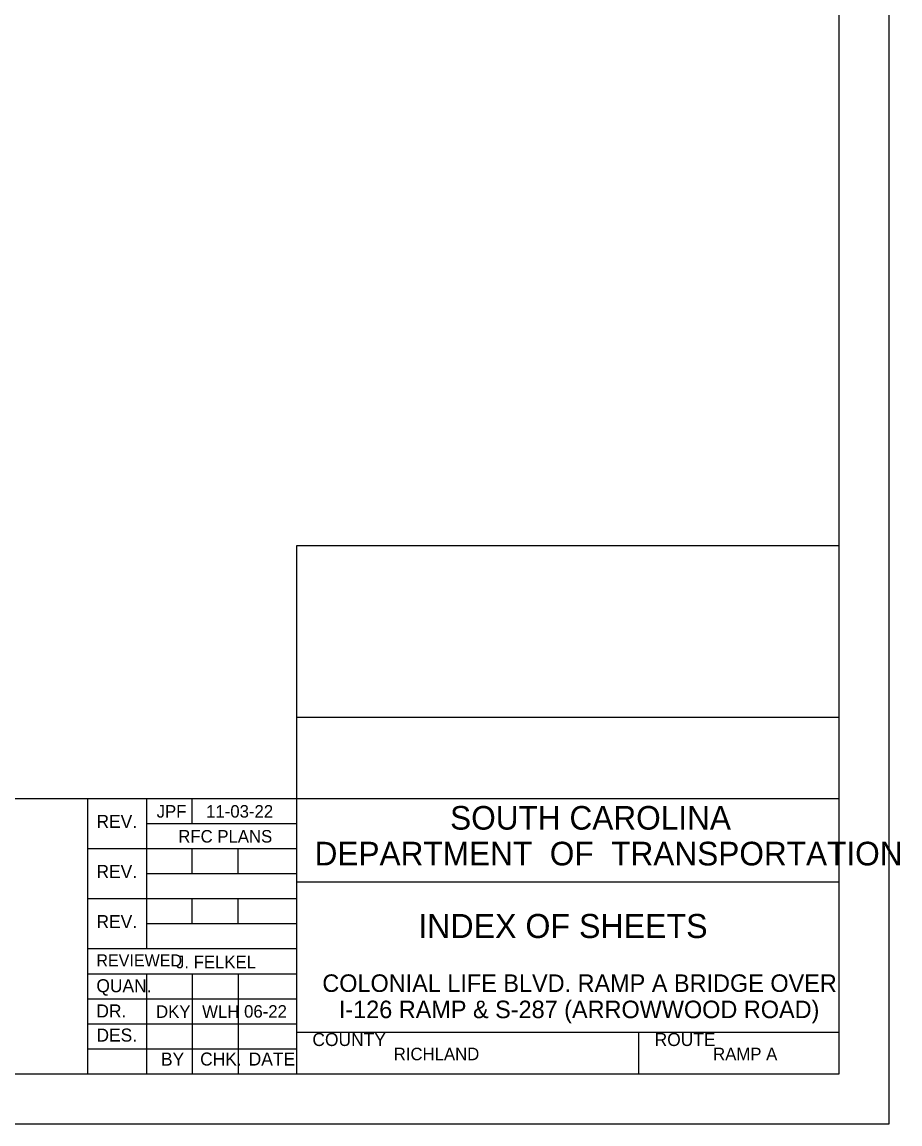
# Model space of a CAD drawing. Extents: x -125.5 to -89.4, y -5.1 to 16.9.
# Drawn here: x -98.19 to -89.43, y -5.07 to 5.93 of the extents above; entities that cross this region are included whole.
import ezdxf

# ---------------------------------------------------------------- set-up
doc = ezdxf.new("R2010")
doc.units = 0
for name, color, linetype in [('BR_BORDER LINES', 7, 'Continuous'), ('BR_TEXT', 7, 'Continuous'), ('Level 31', 7, 'Continuous')]:
    doc.layers.add(name, color=color, linetype=linetype)

msp = doc.modelspace()

# ---------------------------------------------------------------- linework, layer by layer
at = {"layer": 'BR_BORDER LINES'}
for p, q in [((-90.033, -4.566), (-90.033, 16.434)), ((-95.45, -4.566), (-95.45, 0.71)), ((-95.45, 0.71), (-90.033, 0.71)), ((-95.45, -1.004), (-90.033, -1.004)), ((-102.899, -1.816), (-97.534, -1.816)), ((-97.534, -4.566), (-97.534, -1.816)), ((-97.534, -1.816), (-90.033, -1.816)), ((-96.95, -1.816), (-96.95, -3.316)), ((-96.492, -2.066), (-96.492, -1.816)), ((-96.95, -2.066), (-95.45, -2.066)), ((-97.534, -2.316), (-95.45, -2.316)), ((-96.492, -2.566), (-96.492, -2.316)), ((-96.034, -2.566), (-96.034, -2.316)), ((-96.95, -2.566), (-95.45, -2.566)), ((-95.45, -2.649), (-95.45, -2.649)), ((-95.45, -2.649), (-90.033, -2.649)), ((-97.534, -2.816), (-95.45, -2.816)), ((-96.492, -3.066), (-96.492, -2.816)), ((-96.034, -3.066), (-96.034, -2.816)), ((-96.95, -3.066), (-95.45, -3.066)), ((-97.534, -3.316), (-95.45, -3.316)), ((-97.534, -3.566), (-95.45, -3.566)), ((-96.95, -3.566), (-96.95, -4.566)), ((-96.492, -3.566), (-96.492, -4.566)), ((-96.034, -3.566), (-96.034, -4.566)), ((-97.534, -3.816), (-95.45, -3.816)), ((-97.534, -4.066), (-95.45, -4.066)), ((-95.45, -4.149), (-90.033, -4.149)), ((-95.353, -4.149), (-90.033, -4.149)), ((-92.033, -4.566), (-92.033, -4.149)), ((-97.534, -4.316), (-95.45, -4.316)), ((-123.699, -4.566), (-90.033, -4.566))]:
    msp.add_line(p, q, dxfattribs=at)
at = {"layer": 'Level 31'}
msp.add_line((-92.742, -3.09), (-92.742, -3.09), dxfattribs=at)
msp.add_lwpolyline([(-125.533, 16.934), (-125.533, -5.066), (-89.533, -5.066), (-89.533, 16.934)], dxfattribs=at)

# ---------------------------------------------------------------- texts
at = {"layer": 'BR_TEXT'}
for s, height, p in [('JPF', 0.125, (-96.848, -2.008)), ('11-03-22', 0.125, (-96.354, -2.008)), ('SOUTH CAROLINA', 0.23587, (-93.918, -2.128)), ('REV.', 0.13, (-97.449, -2.111)), ('RFC PLANS', 0.125, (-96.632, -2.257)), ('DEPARTMENT  OF  TRANSPORTATION', 0.23587, (-95.271, -2.485)), ('REV.', 0.13, (-97.449, -2.611)), ('INDEX OF SHEETS', 0.24, (-94.236, -3.21)), ('REV.', 0.13, (-97.449, -3.111)), ('REVIEWED', 0.12, (-97.45, -3.493)), ('J. FELKEL', 0.125, (-96.655, -3.512)), ('QUAN.', 0.13, (-97.45, -3.751)), ('COLONIAL LIFE BLVD. RAMP A BRIDGE OVER', 0.175, (-95.194, -3.748)), ('I-126 RAMP & S-287 (ARROWWOOD ROAD)', 0.175, (-95.029, -4.01)), ('DR.', 0.13, (-97.45, -4.003)), ('DKY', 0.125, (-96.854, -4.007)), ('WLH', 0.125, (-96.394, -4.007)), ('06-22', 0.125, (-95.975, -4.005)), ('DES.', 0.13, (-97.449, -4.244)), ('COUNTY', 0.13, (-95.293, -4.288)), ('ROUTE', 0.13, (-91.876, -4.288)), ('BY', 0.13, (-96.805, -4.484)), ('CHK.', 0.13, (-96.414, -4.483)), ('DATE', 0.13, (-95.929, -4.483)), ('RICHLAND', 0.125, (-94.481, -4.43)), ('RAMP A', 0.125, (-91.292, -4.43))]:
    msp.add_text(s, height=height, dxfattribs=at).set_placement(p)

doc.saveas('drawing.dxf')
